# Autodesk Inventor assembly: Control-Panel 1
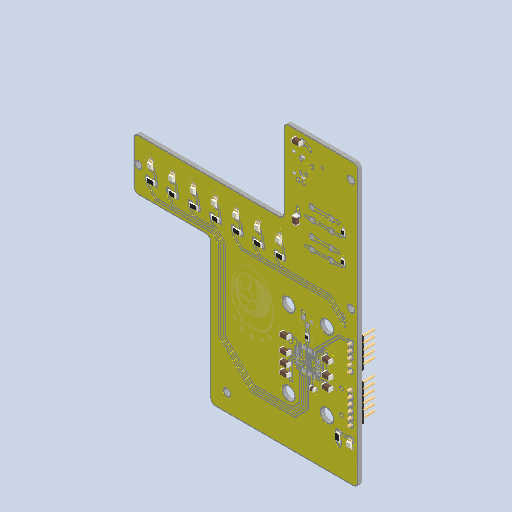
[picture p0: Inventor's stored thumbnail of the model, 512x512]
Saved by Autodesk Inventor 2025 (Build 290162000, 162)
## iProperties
Company: Kicad
Created: 2026-09
Part Number: Control-Panel 1
Description: KiCad electronic assembly
Document SubType Name: Assembly
Designer: Leonardo
Authority: Unknown
Title: Control-Panel.step
Author: Pcbnew
Sending System: KiCad to STEP converter
Preprocessor: Open CASCADE STEP processor 7.9
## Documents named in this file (19)
- C:\Users\Leonardo\Documents\Control-Panel\Control-Panel\Control-Panel.iam
- C:\Users\Leonardo\Documents\Control-Panel\Control-Panel\C_1206_3216Metric.ipt
- C:\Users\Leonardo\Documents\Control-Panel\Control-Panel\R_1206_3216Metric.ipt
- C:\Users\Leonardo\Documents\Control-Panel\Control-Panel\R_0805_2012Metric.ipt
- C:\Users\Leonardo\Documents\Control-Panel\Control-Panel\LED_1206_3216Metric.ipt
- C:\Users\Leonardo\Documents\Control-Panel\Control-Panel\C_0805_2012Metric.ipt
- C:\Users\Leonardo\Documents\Control-Panel\Control-Panel\PinHeader_1x06_P2.54mm_Vertical.ipt
- C:\Users\Leonardo\Documents\Control-Panel\Control-Panel\PinHeader_1x05_P2.54mm_Vertical.ipt
- C:\Users\Leonardo\Documents\Control-Panel\Control-Panel\SOT-23-6.ipt
- C:\Users\Leonardo\Documents\Control-Panel\Control-Panel\Fuse_1206_3216Metric.ipt
- C:\Users\Leonardo\Documents\Control-Panel\Control-Panel\SOT-223.ipt
- C:\Users\Leonardo\Documents\Control-Panel\Control-Panel\Control-Panel_copper.ipt
- C:\Users\Leonardo\Documents\Control-Panel\Control-Panel\Control-Panel_pad.ipt
- C:\Users\Leonardo\Documents\Control-Panel\Control-Panel\Control-Panel_via.ipt
- C:\Users\Leonardo\Documents\Control-Panel\Control-Panel\Control-Panel_silkscreen.ipt
- C:\Users\Leonardo\Documents\Control-Panel\Control-Panel\Control-Panel_silkscreen_1.ipt
- C:\Users\Leonardo\Documents\Control-Panel\Control-Panel\Control-Panel_soldermask.ipt
- C:\Users\Leonardo\Documents\Control-Panel\Control-Panel\Control-Panel_soldermask_1.ipt
- C:\Users\Leonardo\Documents\Control-Panel\Control-Panel\Control-Panel_PCB.ipt
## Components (46 placed, 46 different names)
1. 1
2. 2
3. 3
4. 4
5. 5
6. 6
7. 7
8. 8
9. 9
10. 10
11. 11
12. 12
13. 13
14. 14
15. 15
16. 16
17. 17
18. 18
19. 19
20. 20
21. 21
22. 22
23. 23
24. 24
25. 25
26. 26
27. 27
28. 28
29. 29
30. 30
31. 31
32. 32
33. 33
34. 34
35. 35
36. 36
37. 37
38. 38
39. 39
40. 40
41. 41
42. 42
43. 43
44. 44
45. 45
46. 46
